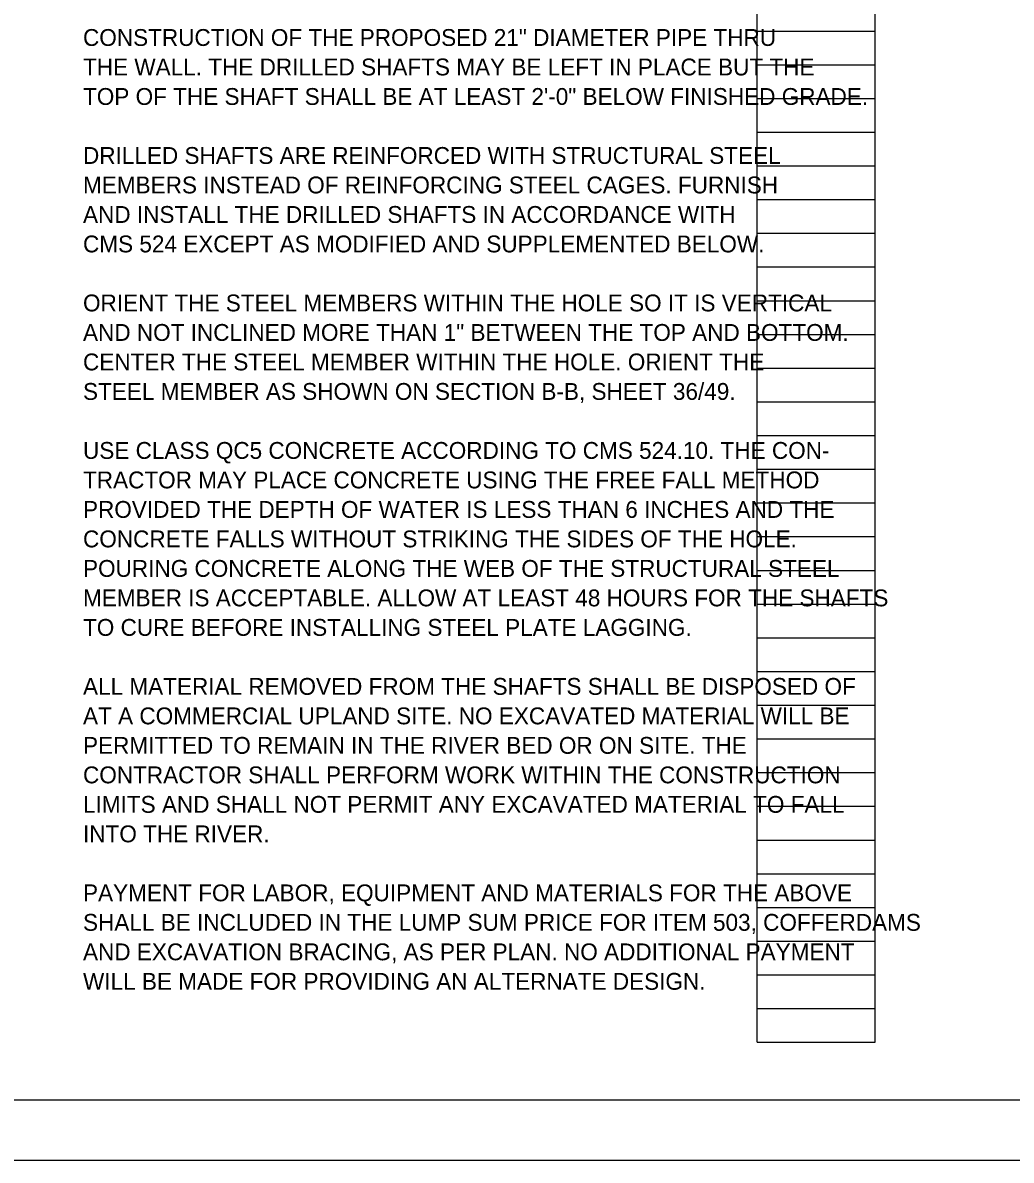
# Model space of a CAD drawing. Extents: x 0 to 34, y 0 to 22.
# Drawn here: x 17.58 to 25.79, y 0 to 9.45 of the extents above; entities that cross this region are included whole.
import ezdxf

# ---------------------------------------------------------------- set-up
doc = ezdxf.new("R2010")
doc.units = 0
for name, color, linetype in [('BR_P_Gen_Text', 7, 'Continuous'), ('SC_Scratch9', 7, 'Continuous'), ('SH_Border', 7, 'Continuous'), ('SH_Cut_Line', 7, 'Continuous')]:
    doc.layers.add(name, color=color, linetype=linetype)

msp = doc.modelspace()

# ---------------------------------------------------------------- linework, layer by layer
at = {"layer": 'SC_Scratch9'}
for p, q in [((23.68, 0.98), (23.68, 21.14)), ((24.66, 0.98), (24.66, 21.14)), ((23.68, 9.38), (24.66, 9.38)), ((23.68, 9.1), (24.66, 9.1)), ((23.68, 8.82), (24.66, 8.82)), ((23.68, 8.54), (24.66, 8.54)), ((23.68, 8.26), (24.66, 8.26)), ((23.68, 7.98), (24.66, 7.98)), ((23.68, 7.7), (24.66, 7.7)), ((23.68, 7.42), (24.66, 7.42)), ((23.68, 7.14), (24.66, 7.14)), ((23.68, 6.86), (24.66, 6.86)), ((23.68, 6.58), (24.66, 6.58)), ((23.68, 6.3), (24.66, 6.3)), ((23.68, 6.02), (24.66, 6.02)), ((23.68, 5.74), (24.66, 5.74)), ((23.68, 5.46), (24.66, 5.46)), ((23.68, 5.18), (24.66, 5.18)), ((23.68, 4.9), (24.66, 4.9)), ((23.68, 4.62), (24.66, 4.62)), ((23.68, 4.34), (24.66, 4.34)), ((23.68, 4.06), (24.66, 4.06)), ((23.68, 3.78), (24.66, 3.78)), ((23.68, 3.5), (24.66, 3.5)), ((23.68, 3.22), (24.66, 3.22)), ((23.68, 2.94), (24.66, 2.94)), ((23.68, 2.66), (24.66, 2.66)), ((23.68, 2.38), (24.66, 2.38)), ((23.68, 2.1), (24.66, 2.1)), ((23.68, 1.82), (24.66, 1.82)), ((23.68, 1.54), (24.66, 1.54)), ((23.68, 1.26), (24.66, 1.26)), ((23.68, 0.98), (24.66, 0.98))]:
    msp.add_line(p, q, dxfattribs=at)
at = {"layer": 'SH_Border'}
msp.add_lwpolyline([(1.5, 21.5), (33.5, 21.5), (33.5, 0.5), (1.5, 0.5)], close=True, dxfattribs=at)
at = {"layer": 'SH_Cut_Line'}
msp.add_lwpolyline([(0, 0), (34, 0), (34, 22), (0, 22)], close=True, dxfattribs=at)

# ---------------------------------------------------------------- texts
at = {"layer": 'BR_P_Gen_Text'}
for s, p in [('CONSTRUCTION OF THE PROPOSED 21" DIAMETER PIPE THRU ', (18.0805, 9.256)), ('THE WALL. THE DRILLED SHAFTS MAY BE LEFT IN PLACE BUT THE', (18.0805, 9.011)), ('TOP OF THE SHAFT SHALL BE AT LEAST 2\'-0" BELOW FINISHED GRADE.', (18.0805, 8.766)), ('DRILLED SHAFTS ARE REINFORCED WITH STRUCTURAL STEEL ', (18.0805, 8.276)), ('MEMBERS INSTEAD OF REINFORCING STEEL CAGES. FURNISH ', (18.0805, 8.031)), ('AND INSTALL THE DRILLED SHAFTS IN ACCORDANCE WITH ', (18.0805, 7.786)), ('CMS 524 EXCEPT AS MODIFIED AND SUPPLEMENTED BELOW.', (18.0805, 7.541)), ('ORIENT THE STEEL MEMBERS WITHIN THE HOLE SO IT IS VERTICAL', (18.0805, 7.051)), ('AND NOT INCLINED MORE THAN 1" BETWEEN THE TOP AND BOTTOM. ', (18.0805, 6.806)), ('CENTER THE STEEL MEMBER WITHIN THE HOLE. ORIENT THE ', (18.0805, 6.561)), ('STEEL MEMBER AS SHOWN ON SECTION B-B, SHEET 36/49.', (18.0805, 6.316)), ('USE CLASS QC5 CONCRETE ACCORDING TO CMS 524.10. THE CON-', (18.0805, 5.826)), ('TRACTOR MAY PLACE CONCRETE USING THE FREE FALL METHOD ', (18.0805, 5.581)), ('PROVIDED THE DEPTH OF WATER IS LESS THAN 6 INCHES AND THE', (18.0805, 5.336)), ('CONCRETE FALLS WITHOUT STRIKING THE SIDES OF THE HOLE. ', (18.0805, 5.091)), ('POURING CONCRETE ALONG THE WEB OF THE STRUCTURAL STEEL', (18.0805, 4.846)), ('MEMBER IS ACCEPTABLE. ALLOW AT LEAST 48 HOURS FOR THE SHAFTS', (18.0805, 4.601)), ('TO CURE BEFORE INSTALLING STEEL PLATE LAGGING.', (18.0805, 4.356)), ('ALL MATERIAL REMOVED FROM THE SHAFTS SHALL BE DISPOSED OF ', (18.0805, 3.866)), ('AT A COMMERCIAL UPLAND SITE. NO EXCAVATED MATERIAL WILL BE ', (18.0805, 3.621)), ('PERMITTED TO REMAIN IN THE RIVER BED OR ON SITE. THE ', (18.0805, 3.376)), ('CONTRACTOR SHALL PERFORM WORK WITHIN THE CONSTRUCTION', (18.0805, 3.131)), ('LIMITS AND SHALL NOT PERMIT ANY EXCAVATED MATERIAL TO FALL', (18.0805, 2.886)), ('INTO THE RIVER.', (18.0805, 2.641)), ('PAYMENT FOR LABOR, EQUIPMENT AND MATERIALS FOR THE ABOVE', (18.0805, 2.151)), ('SHALL BE INCLUDED IN THE LUMP SUM PRICE FOR ITEM 503, COFFERDAMS', (18.0805, 1.906)), ('AND EXCAVATION BRACING, AS PER PLAN. NO ADDITIONAL PAYMENT', (18.0805, 1.661)), ('WILL BE MADE FOR PROVIDING AN ALTERNATE DESIGN.', (18.0805, 1.416))]:
    msp.add_text(s, height=0.14, dxfattribs=at).set_placement(p)

doc.saveas('drawing.dxf')
